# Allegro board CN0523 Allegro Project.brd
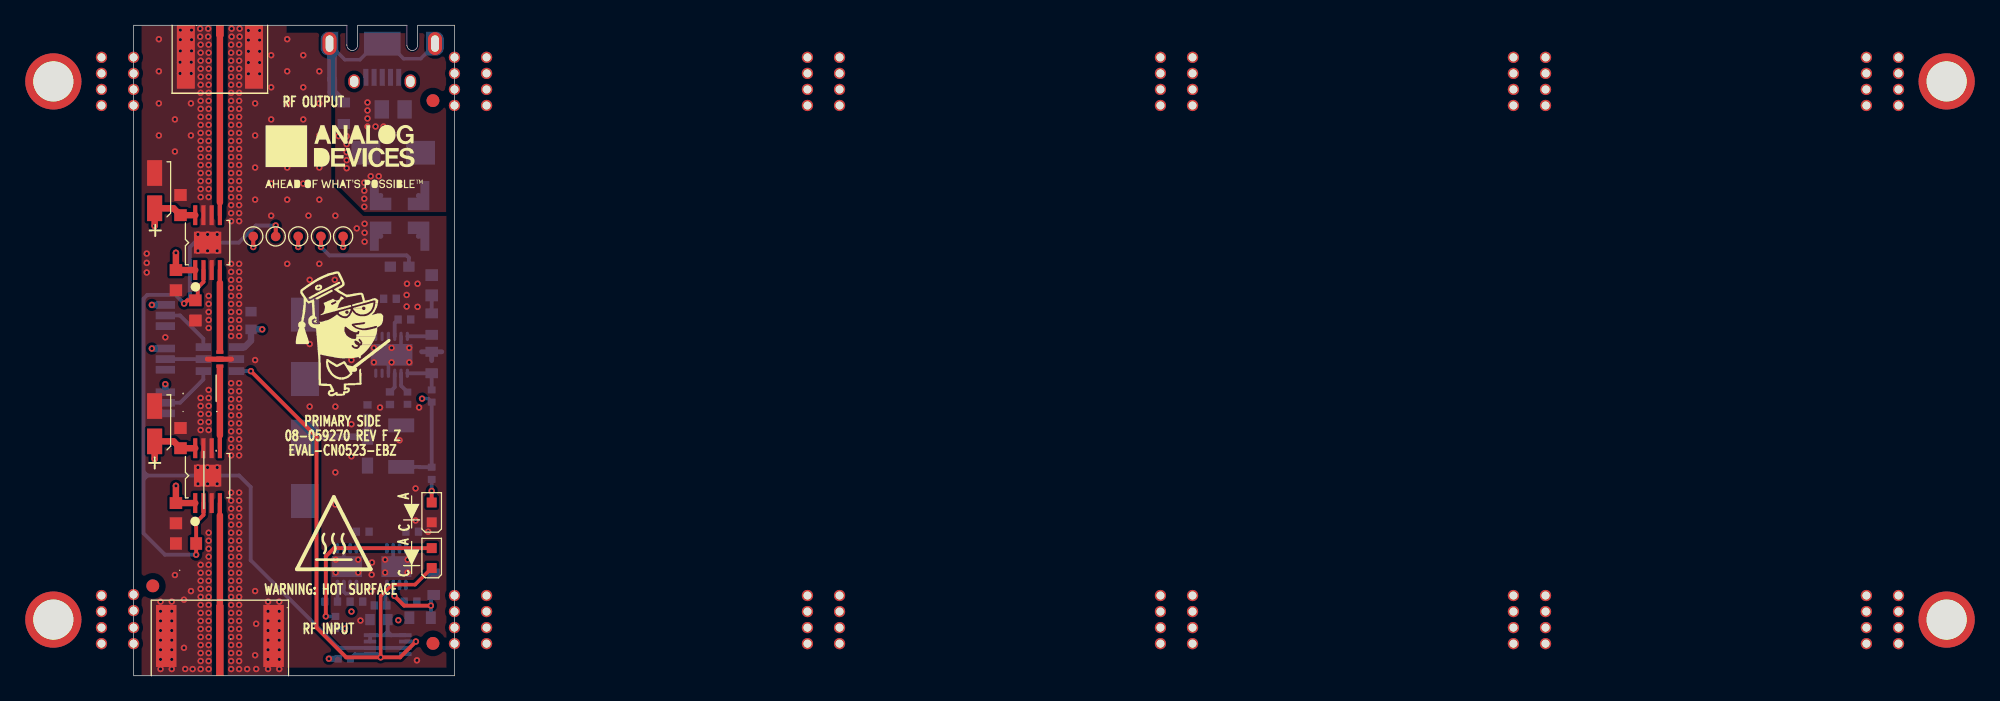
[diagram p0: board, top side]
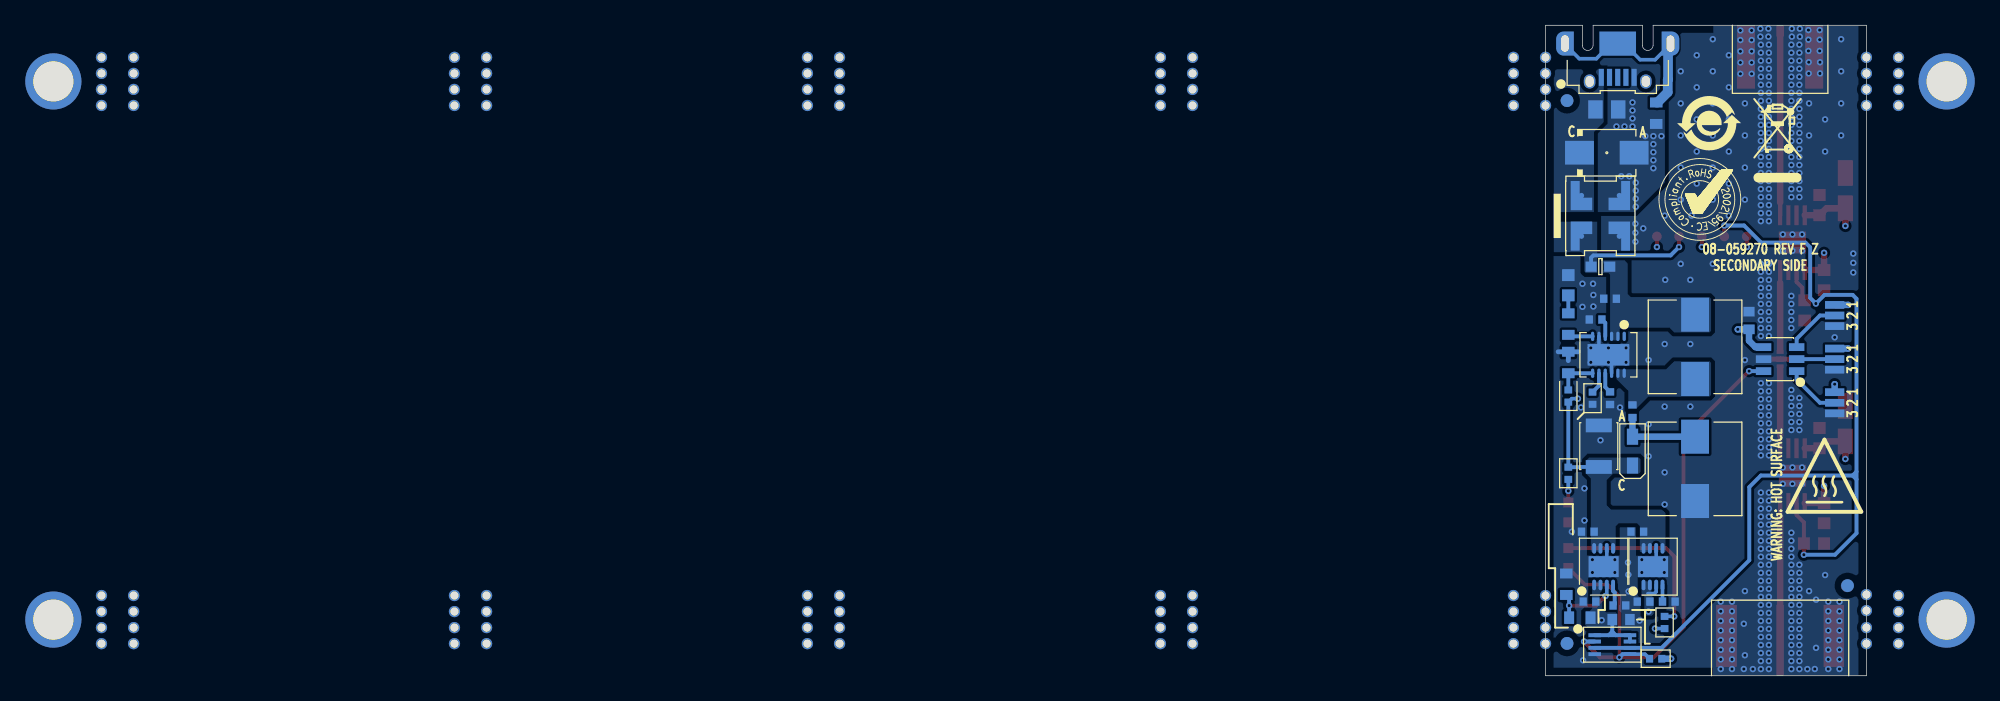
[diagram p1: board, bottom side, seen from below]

Outline 25.4 x 51.49 mm; copper layers: TOP, L2_GND, L3_GND, L4_PWR, L5_GND, BOTTOM. Coordinates in mm from the lower left corner of the outline.
Outline path: 0,51.49 0,0 25.4,0 25.4,51.49 22.49,51.49 22.49,49.92 arc(22.06,49.49) 21.63,49.92 21.63,51.49 17.74,51.49 17.74,49.92 arc(17.31,49.49) 16.88,49.92 16.88,51.49 4.96,51.49 4.97,51.49 0,51.49

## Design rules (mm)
constraint set DEFAULT: min track width 0.279

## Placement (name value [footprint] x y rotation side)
C1  330PF  [C0603]  4.15 10.47 0 top
C2  330PF  [C0603]  3.35 12.87 90 top
C3  330PF  [C0603]  3.71 18.81 270 top
C4  2.2uF  [C3216]  1.67 19.95 90 top
C5  330PF  [C0603]  4.89 28.92 90 top
C6  330PF  [C0603]  3.35 31.32 90 top
C7  330PF  [C0603]  3.71 37.26 270 top
C8  2.2uF  [C3216]  1.67 38.4 90 top
C9  0.1uF  [C0603#2]  9.29 28.12 270 bottom
C10  0.1uF  [C0603#2]  19.42 4.45 0 bottom
C11  4.7uF  [C0402]  18.14 11.4 180 bottom
C12  1000pF  [C0402]  15.64 5.87 0 bottom
C13  4.7uF  [C0402]  17.64 5.87 180 bottom
C23  47UF  [C0805H55]  20.55 44.83 0 bottom
C25  4.7uF  [C0402]  20.29 29.85 180 bottom
C26  3.3NF  [C0603]  23.6 30.91 90 bottom
C27  1uF  [C0402]  21.44 28.2 180 bottom
C28  22UF  [C1210H106]  21.18 18.17 90 bottom
C29  10NF  [C0402]  20.29 21.97 90 bottom
C30  1uF  [C0402]  18.52 20.94 90 bottom
C36  4.7uF  [C0402]  22.05 11.4 180 bottom
C38  1000pF  [C0402]  19.55 5.56 0 bottom
C39  4.7uF  [C0402]  21.92 5.87 180 bottom
D1  SMAJ5.0A-13-F  [DIOSMJ5_0]  20.55 41.4 180 bottom
D2  PMEG3010BEA,115  [SOD323]  18.52 17.78 90 bottom
DS1  150060VS55040  [LED0603-2]  23.6 12.93 90 top
DS2  150060RS55040  [LED0603-2]  23.6 9.32 90 top
E1  120OHM  [L0603]  21.06 32.39 0 bottom
FL1  5.5GHZ  [FL0603-3P-RF]  6.83 25.06 90 top
J1  132365-10  [CNSMARAL686W375H177]  6.83 0 270 top
J2  60312202114513  [CNSMARAL559W250H131]  6.83 51.49 90 top
JP1  3PIN_SOLDER_JUMPER  [JPRSLD03]  2.51 28.52 270 bottom
JP2  3PIN_SOLDER_JUMPER  [JPRSLD03]  2.51 25.06 270 bottom
JP3  3PIN_SOLDER_JUMPER  [JPRSLD03]  2.51 21.61 270 bottom
L3  800OHMS AT 100MEGHZ  [L2020_A]  21.06 36.4 270 bottom
L5  1.5UH  [LSMSQ272H197]  13.56 16.38 270 bottom
L6  1.5UH  [LSMSQ272H197]  13.56 26.04 270 bottom
NOREF  -  []  189.67 175.62 0 top
NOREF#2  -  []  -69.38 311.61 0 top
NOREF#3  -  []  167.86 166.39 0 top
NOREF#4  -  []  18.41 0 90 top
NOREF#5  -  []  55.88 0 0 top
NOREF#6  -  [unnamed#2]  143.51 47.05 0 top
NOREF#7  -  []  -3.73 85.62 0 top
NOREF#8  -  [unnamed#2]  81.28 47.68 0 top
NOREF#9  -  [unnamed#2]  139.7 45.14 0 top
NOREF#10  -  [unnamed#2]  137.16 46.41 0 top
NOREF#11  -  [unnamed#2]  23.7 45.53 0 top
NOREF#12  -  [unnamed#2]  83.82 5.08 0 top
NOREF#13  -  []  45.13 222.88 0 top
NOREF#14  -  []  109.22 0 0 top
NOREF#15  -  [unnamed#2]  0 46.41 0 top
NOREF#16  -  [unnamed#2]  53.34 45.14 0 top
NOREF#17  -  [unnamed#2]  109.22 47.68 0 top
NOREF#18  -  [unnamed#2]  111.76 45.14 0 top
NOREF#19  -  [unnamed#2]  55.88 45.14 0 top
NOREF#20  -  [unnamed#2]  109.22 2.54 0 top
NOREF#21  -  [unnamed#2]  25.4 46.41 0 top
NOREF#22  -  [unnamed#2]  0 6.43 0 top
NOREF#23  -  []  -85.24 -85.99 0 top
NOREF#24  -  []  48.89 171.39 0 top
NOREF#25  -  []  25.02 178.51 0 top
NOREF#26  -  [unnamed#2]  109.22 46.41 0 top
NOREF#27  -  []  40.38 222.88 0 top
NOREF#28  -  [unnamed#2]  53.34 5.08 0 top
NOREF#29  -  [unnamed#2]  -6.35 47.05 0 top
NOREF#30  -  [unnamed#2]  1.52 7.11 0 top
NOREF#31  -  [unnamed#2]  -2.54 6.35 0 top
NOREF#32  -  [unnamed#2]  83.82 46.41 0 top
NOREF#33  -  []  184.92 206.92 90 top
NOREF#34  -  [unnamed#2]  0 48.95 0 top
NOREF#35  -  [unnamed#2]  137.16 45.14 0 top
NOREF#36  -  [unnamed#2]  137.16 5.08 0 top
NOREF#37  -  [unnamed#2]  25.4 47.68 0 top
NOREF#38  -  []  23.49 171.41 0 top
NOREF#39  -  []  53.34 0 0 top
NOREF#40  -  [unnamed#2]  55.88 2.54 0 top
NOREF#41  -  [unnamed#2]  53.34 48.95 0 top
NOREF#42  -  [unnamed#2]  25.4 48.95 0 top
NOREF#43  -  []  48.89 171.39 90 top
NOREF#44  -  [unnamed#2]  109.22 48.95 0 top
NOREF#45  -  [unnamed#2]  53.34 2.54 0 top
NOREF#46  -  [unnamed#2]  81.28 2.54 0 top
NOREF#47  -  [unnamed#2]  139.7 3.81 0 top
NOREF#48  -  [unnamed#2]  55.88 6.35 0 top
NOREF#49  -  []  18.41 51.49 180 top
NOREF#50  -  []  -26.51 203.8 0 top
NOREF#51  -  [unnamed#2]  109.22 45.14 0 top
NOREF#52  -  [unnamed#2]  81.28 45.14 0 top
NOREF#53  -  [unnamed#2]  137.16 3.81 0 top
NOREF#54  -  [unnamed#2]  139.7 46.41 0 top
NOREF#55  -  []  111.76 0 0 top
NOREF#56  -  [unnamed#2]  -2.54 47.68 0 top
NOREF#57  -  [unnamed#2]  83.82 45.14 0 top
NOREF#58  -  [unnamed#2]  0 45.14 0 top
NOREF#59  -  []  81.28 0 0 top
NOREF#60  -  [unnamed#2]  111.76 6.35 0 top
NOREF#61  -  []  0 0 0 top
NOREF#62  -  [unnamed#2]  137.16 2.54 0 top
NOREF#63  -  [unnamed#2]  81.28 6.35 0 top
NOREF#64  -  [unnamed#2]  -2.54 2.54 0 top
NOREF#65  -  [unnamed#2]  0 5.16 0 top
NOREF#66  -  []  -85.24 -85.99 0 top
NOREF#67  -  []  -85.24 -85.99 0 top
NOREF#68  -  [unnamed#2]  0 3.81 0 top
NOREF#69  -  [unnamed#2]  81.28 5.08 0 top
NOREF#70  -  [unnamed#2]  139.7 2.54 0 top
NOREF#71  -  [unnamed#2]  55.88 5.08 0 top
NOREF#72  -  [unnamed#2]  137.16 6.35 0 top
NOREF#73  -  []  194.98 109.04 0 top
NOREF#74  -  []  178.88 195.06 0 top
NOREF#75  -  []  23.49 222.88 0 top
NOREF#76  -  [unnamed#2]  109.22 5.08 0 top
NOREF#77  -  [unnamed#2]  0 47.68 0 top
NOREF#78  -  [unnamed#2]  27.94 48.95 0 top
NOREF#79  -  []  137.16 0 0 top
NOREF#80  -  []  0 0 0 top
NOREF#81  -  [unnamed#2]  111.76 47.68 0 top
NOREF#82  -  [unnamed#2]  -2.54 5.08 0 top
NOREF#83  -  [unnamed#2]  55.88 47.68 0 top
NOREF#84  -  []  176.52 177.28 90 top
NOREF#85  -  [unnamed#2]  83.82 2.54 0 top
NOREF#86  -  []  147.32 0 0 top
NOREF#87  -  [unnamed#2]  111.76 2.54 0 top
NOREF#88  -  [unnamed#2]  143.51 4.45 0 top
NOREF#89  -  [unnamed#2]  111.76 3.81 0 top
NOREF#90  -  [unnamed#2]  111.76 48.95 0 top
NOREF#91  -  []  83.82 0 0 top
NOREF#92  -  []  25.4 0 0 top
NOREF#93  -  [unnamed#2]  55.88 48.95 0 top
NOREF#94  -  []  181.24 212.84 90 top
NOREF#95  -  [unnamed#2]  109.22 6.35 0 top
NOREF#96  -  [unnamed#2]  53.34 46.41 0 top
NOREF#97  -  [unnamed#2]  27.94 3.81 0 top
NOREF#98  -  [unnamed#2]  -2.54 3.81 0 top
NOREF#99  -  [unnamed#2]  25.4 5.08 0 top
NOREF#100  -  [unnamed#2]  111.76 5.08 0 top
NOREF#101  -  [unnamed#2]  139.7 48.95 0 top
NOREF#102  -  []  -2.54 0 0 top
NOREF#103  -  [unnamed#2]  53.34 3.81 0 top
NOREF#104  -  [unnamed#2]  81.28 3.81 0 top
NOREF#105  -  []  14.14 -9.55 0 top
NOREF#106  -  []  -10.16 0 0 top
NOREF#107  -  []  -6.35 4.45 0 top
NOREF#108  -  [unnamed#2]  27.94 6.35 0 top
NOREF#109  -  [unnamed#2]  139.7 47.68 0 top
NOREF#110  -  [unnamed#2]  139.7 6.35 0 top
NOREF#111  -  []  39.96 219.32 0 top
NOREF#112  -  [unnamed#2]  0 2.54 0 top
NOREF#113  -  [unnamed#2]  83.82 48.95 0 top
NOREF#114  -  [unnamed#2]  83.82 6.35 0 top
NOREF#115  -  [unnamed#2]  109.22 3.81 0 top
NOREF#116  -  [unnamed#2]  27.94 5.08 0 top
NOREF#117  -  [unnamed#2]  55.88 46.41 0 top
NOREF#118  -  []  23.49 222.88 0 top
NOREF#119  -  [unnamed#2]  137.16 47.68 0 top
NOREF#120  -  [unnamed#2]  -2.54 48.95 0 top
NOREF#121  -  [unnamed#2]  111.76 46.41 0 top
NOREF#122  -  []  139.7 0 0 top
NOREF#123  -  [unnamed#2]  83.82 47.68 0 top
NOREF#124  -  [unnamed#2]  27.94 45.14 0 top
NOREF#125  -  []  46.05 222.88 0 top
NOREF#126  -  [unnamed#2]  27.94 2.54 0 top
NOREF#127  -  [unnamed#2]  25.4 2.54 0 top
NOREF#128  -  [unnamed#2]  25.4 45.14 0 top
NOREF#129  -  []  16.36 41.07 0 top
NOREF#130  -  [unnamed#2]  27.94 46.41 0 top
NOREF#131  -  []  27.94 0 0 top
NOREF#132  -  []  0 51.49 270 top
NOREF#133  -  [unnamed#2]  81.28 48.95 0 top
NOREF#134  -  [unnamed#2]  -2.54 45.14 0 top
NOREF#135  -  [unnamed#2]  137.16 48.95 0 top
NOREF#136  -  [unnamed#2]  81.28 46.41 0 top
NOREF#137  -  []  25.02 178.51 0 top
NOREF#138  -  []  -10.16 0 0 top
NOREF#139  -  []  -10.16 51.49 0 top
NOREF#140  -  []  23.49 171.41 0 top
NOREF#141  -  [unnamed#2]  53.34 6.35 0 top
NOREF#142  -  [unnamed#2]  139.7 5.08 0 top
NOREF#143  -  []  178.88 209.23 0 top
NOREF#144  -  [unnamed#2]  -2.54 46.41 0 top
NOREF#145  -  [unnamed#2]  55.88 3.81 0 top
NOREF#146  -  [unnamed#2]  25.4 3.81 0 top
NOREF#147  -  []  16.59 27.07 0 top
NOREF#148  -  []  167.86 206.94 0 top
NOREF#149  -  []  41.23 222.88 0 top
NOREF#150  -  [unnamed#2]  -6.35 4.45 0 top
NOREF#151  -  [unnamed#2]  23.7 2.56 0 top
NOREF#152  -  [unnamed#2]  83.82 3.81 0 top
NOREF#153  -  []  10.01 92.28 0 top
NOREF#154  -  [unnamed#2]  53.34 47.68 0 top
NOREF#155  -  [unnamed#2]  25.4 6.35 0 top
NOREF#156  -  []  -6.35 4.45 0 top
NOREF#157  -  [unnamed#2]  27.94 47.68 0 top
NOREF#158  -  [unnamed#2]  1.5 7.13 180 bottom
NOREF#159  -  [unnamed#2]  23.7 45.53 180 bottom
NOREF#160  -  []  7.24 39.12 180 bottom
NOREF#161  -  [unnamed#2]  23.7 2.56 180 bottom
NOREF#162  -  []  13.72 48.77 180 bottom
P1  47590-0001  [CNMOLEX47590-0001]  19.69 51.49 270 bottom
R1  1K  [R0603]  16.64 44.53 270 bottom
R2  10K  [R0402]  16.68 1.35 0 bottom
R3  20K  [R0402]  21.68 21.97 90 bottom
R4  22.1K  [R0603]  23.6 27.84 90 bottom
R5  1MEG  [R0402]  23.6 22.14 90 bottom
R6  402K  [R0603]  23.6 24.8 90 bottom
R7  619  [R0402]  15.98 4.22 270 bottom
R8  150  [R0402]  23.6 16.03 90 bottom
R9  1K  [R0603]  22.68 4.6 0 bottom
R10  6.49K  [R0603]  23.75 7.24 90 bottom
TP1  TESTPAD  [TPSMC30]  11.25 34.78 0 top
TP2  TESTPAD  [TPSMC30]  14.83 34.78 0 top
TP3  TESTPAD  [TPSMC30]  9.47 34.78 0 top
TP4  TESTPAD  [TPSMC30]  13.03 34.78 0 top
TP5  TESTPAD  [TPSMC30]  16.59 34.78 0 top
U1  ADT6401SRJZ  [TSOT23_6]  6.83 25.06 90 bottom
U2  LT8364EDE#PBF  [DFN12_4X3_PAD3_3X1_7]  20.42 25.41 0 bottom
U3  NLV27WZ126USG  [US8-2]  20.11 2.46 270 bottom
U4  ADM7170ACPZ-3.3  [DFN8_3X3_PAD2_38X1_64]  20.8 8.64 180 bottom
U5  ADM7171ACPZ-5.0  [DFN8_3X3_PAD2_38X1_64]  16.89 8.64 180 bottom
U6  HMC407MS8GE  [MSOP8_PAD2_16X1_73]  5.86 15.84 0 top
U7  HMC407MS8GE  [MSOP8_PAD2_16X1_73]  5.86 34.29 0 top

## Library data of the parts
C1-C3 C5-C7 = CAP: User Part Number: UPN; Tolerance: 5; alternate symbols: (C0603); part number: CAP_SM-330PF,50V,5,E042934,C0603; tolerance: 5
C4 C8 = CAPP: Tolerance: 10; User Part Number: UPN; alternate symbols: (C3216); part number: CAPP_SM-2.2UF,25V,10,E000692,C3216; tolerance: 10
C9 C10 = CAP: User Part Number: UPN; Tolerance: 10; alternate symbols: (C0603L); part number: CAP_SM-0.1UF,16V,10,E015036,C0603; tolerance: 10
C11 C13 C25 C36 C39 = CAP: User Part Number: UPN; Tolerance: 20; alternate symbols: (C0402); part number: CAP_SM-4.7UF,6.3V,20,E014207,C0402; tolerance: 20
C12 C38 = CAP: User Part Number: UPN; Tolerance: 5; alternate symbols: (C0402); part number: CAP_SM-1000PF,50V,5,E012419,C0402; tolerance: 5
C23 = CAP: User Part Number: UPN; Tolerance: 20; alternate symbols: (C0805H55); part number: CAP_SM-47UF,6.3V,20,E048007,C0805H55; tolerance: 20
C26 = CAP: User Part Number: UPN; Tolerance: 10; alternate symbols: (C0603); part number: CAP_SM-3.3NF,50V,10,E060118,C0603; tolerance: 10
C27 C30 = CAP: User Part Number: UPN; Tolerance: 20; alternate symbols: (C0402); part number: CAP_SM-1UF,16V,20,E020695,C0402; tolerance: 20
C28 = CAP: Tolerance: 10; User Part Number: UPN; alternate symbols: (C1210H106); part number: CAP_SM-22UF,25V,10,E054041,C1210H106; tolerance: 10
C29 = CAP: User Part Number: UPN; Tolerance: 5; alternate symbols: (C0402); part number: CAP_SM-10NF,16V,5,E042671,C0402; tolerance: 5
D1 = DIO: Tolerance: N/A; User Part Number: UPN; alternate symbols: (DIOSMJ5_0); part number: DIO_SM-SMAJ5.0A-13-F,5V,N/A,E001108,DIOSMJ5_0; tolerance: N/A
D2 = DIOSCHOTTKY: Tolerance: N/A; User Part Number: UPN; alternate symbols: (SOD323); part number: DIOSCHOTTKY_SM-PMEG3010BEA,115,30V,N/A,E014012,SOD323; tolerance: N/A
DS1 = DIOLED: Tolerance: N/A; User Part Number: UPN; alternate symbols: (LED0603-2); part number: DIOLED_SM-150060VS55040,2.4V,N/A,E056632,LED0603-2; tolerance: N/A
DS2 = DIOLED: Tolerance: N/A; User Part Number: UPN; alternate symbols: (LED0603-2); part number: DIOLED_SM-150060RS55040,2.4V,N/A,E056631,LED0603-2; tolerance: N/A
E1 = FERRITE: Tolerance: 25; User Part Number: UPN; alternate symbols: (L0603); part number: FERRITE_SM-120OHM,25,E012242,L0603; tolerance: 25
FL1 = FLTRBP3P_V6: User Part Number: UPN; Tolerance: N/A; alternate symbols: (FL0603-3P-RF); part number: FLTRBP3P_V6_SM-5.5GHZ,E060424,FL0603-3P-RF; tolerance: N/A
J1 = CNBNC5P: Tolerance: N/A; User Part Number: UPN; alternate symbols: (CNSMARAL686W375H177_HMC407); part number: CNBNC5P_SM-132365-10,E033180,CNSMARAL686W375H177; tolerance: N/A
J2 = CNBNC5P: User Part Number: UPN; Tolerance: N/A; alternate symbols: (CNSMARAL559W250H131); part number: CNBNC5P_SM-60312202114513,E049020,CNSMARAL559W250H131; tolerance: N/A
JP1-JP3 = NC3P_JMPR: Tolerance: N/A; User Part Number: UPN; alternate symbols: (JPRSLD03); part number: NC3P_JMPR_SM-3PIN_SOLDER_JUMPER,E005606,JPRSLD03; tolerance: N/A
L3 = CHOKE4P: User Part Number: UPN; Tolerance: N/A; alternate symbols: (L2020_A); part number: CHOKE4P_SM-800OHMS AT 100MEGHZ,N/A,E027130,L2020_A; tolerance: N/A
L5 L6 = IND: Tolerance: 20; User Part Number: UPN; alternate symbols: (LSMSQ272H197); part number: IND_SM-1.5UH,20,E044944,LSMSQ272H197; tolerance: 20
P1 = CN5P_3SHLD: User Part Number: UPN; Tolerance: N/A; alternate symbols: (CNMOLEX47590-0001); part number: CN5P_3SHLD_SM-47590-0001,E015753,CNMOLEX47590-0001; tolerance: N/A
R1 R9 = RES: User Part Number: UPN; Tolerance: 1; alternate symbols: (R0603); part number: RES_SM-1K,E003678,1/10W,1,R0603; tolerance: 1
R2 = RES: Tolerance: 1; User Part Number: UPN; alternate symbols: (R0402); part number: RES_SM-10K,E003751,1/10W,1,R0402; tolerance: 1
R3 = RES: Tolerance: 1; User Part Number: UPN; alternate symbols: (R0402); part number: RES_SM-20K,E003791,1/10W,1,R0402; tolerance: 1
R4 = RES: User Part Number: UPN; Tolerance: 1; alternate symbols: (R0603); part number: RES_SM-22.1K,E003681,1/10W,1,R0603; tolerance: 1
R5 = RES: Tolerance: 1; User Part Number: UPN; alternate symbols: (R0402); part number: RES_SM-1MEG,E003749,1/10W,1,R0402; tolerance: 1
R6 = RES: User Part Number: UPN; Tolerance: 1; alternate symbols: (R0603); part number: RES_SM-402K,E026771,1/10W,1,R0603; tolerance: 1
R7 = RES: Tolerance: 1; User Part Number: UPN; alternate symbols: (R0402); part number: RES_SM-619,E006549,1/10W,1,R0402; tolerance: 1
R8 = RES: Tolerance: 1; User Part Number: UPN; alternate symbols: (R0402); part number: RES_SM-150,E017444,1/10W,1,R0402; tolerance: 1
R10 = RES: User Part Number: UPN; Tolerance: 1; alternate symbols: (R0603); part number: RES_SM-6.49K,E050706,1/10W,1,R0603; tolerance: 1
TP1-TP5 = NCTESTPAD: Tolerance: N/A; User Part Number: UPN; alternate symbols: (TPSMC30); part number: NCTESTPAD_SM-TESTPAD,E012884,TPSMC30; tolerance: N/A
U1 = ADT6401: User Part Number: UPN; Tolerance: N/A; alternate symbols: (TSOT23_6); part number: ADT6401_SM-ADT6401SRJZ,E038244,TSOT23_6; tolerance: N/A
U2 = ADLT8364_V2: User Part Number: UPN; Tolerance: N/A; alternate symbols: (DFN12_4X3_PAD3_3X1_7); part number: ADLT8364_V2_SM-LT8364EDE#PBF,E038568,DFN12_4X3_PAD3_3X1_7; tolerance: N/A
U3 = ICNL27WZ126: Tolerance: N/A; User Part Number: UPN; alternate symbols: (US8-2); part number: ICNL27WZ126_SM-NLV27WZ126USG,E060395,US8-2; tolerance: N/A
U4 = ADM7170: Tolerance: N/A; User Part Number: UPN; alternate symbols: (DFN8_3X3_PAD2_38X1_64); part number: ADM7170_SM-ADM7170ACPZ-3.3,E022590,DFN8_3X3_PAD2_38X1_64; tolerance: N/A
U5 = ADM7171: Tolerance: N/A; User Part Number: UPN; alternate symbols: (DFN8_3X3_PAD2_38X1_64); part number: ADM7171_SM-ADM7171ACPZ-5.0,E022768,DFN8_3X3_PAD2_38X1_64; tolerance: N/A
U6 U7 = ADHMC407: Tolerance: N/A; User Part Number: UPN; alternate symbols: (MSOP8_PAD2_16X1_73); part number: ADHMC407_SM-HMC407MS8GE,E055304,MSOP8_PAD2_16X1_73; tolerance: N/A

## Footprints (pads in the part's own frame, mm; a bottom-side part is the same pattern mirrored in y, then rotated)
C0402
  rect 0.584x0.66 smd: 1(-0.5,0) 2(0.5,0)
C0603
  rect 0.94x0.991 smd: 1(-0.8,0) 2(0.8,0)
C0603#2
  rect 0.762x0.889 smd: 1(-0.7,0) 2(0.7,0)
C0805H55
  rect 1.143x1.448 smd: 1(-0.9,0) 2(0.9,0)
C1210H106
  rect 1.092x2.057 smd: 1(-1.646,0) 2(1.646,0)
C3216
  rect 2.032x1.194 smd: N(1.397,0) P(-1.397,0)
CNMOLEX47590-0001
  oval 1.118x0.914 hole 0.864x0.66: (4.45,-2.225) (4.45,2.225)
  rect 1.346x0.406 smd: 1(4.123,-1.3) 2(4.123,-0.65) 3(4.123,0) 4(4.123,0.65) 5(4.123,1.3)
  oval 1.803x1.118 hole 1.295x0.61: SH1(1.45,4.175) SH3(1.45,-4.175)
  rect 1.905x2.896 smd: SH2(1.45,0)
CNSMARAL559W250H131
  rect 0.889x0.61 smd: 1(-0.445,0)
  rect 5.004x1.397 smd: 2(-2.502,2.702) 3(-2.502,-2.702) 4(-2.502,2.702) 5(-2.502,-2.702)
CNSMARAL686W375H177
  rect 5.613x0.584 smd: 1(-2.807,0)
  rect 4.902x1.6 smd: 2(-3.151,4.25) 3(-3.151,4.25) 4(-3.151,-4.25) 5(-3.151,-4.25)
DFN8_3X3_PAD2_38X1_64
  oval 0.305x0.838 smd: 1(-0.75,-1.45) 2(-0.25,-1.45) 3(0.25,-1.45) 4(0.75,-1.45) 5(0.75,1.45) 6(0.25,1.45) 7(-0.25,1.45) 8(-0.75,1.45)
  rect 2.388x1.651 smd: PAD(0,0)
DFN12_4X3_PAD3_3X1_7
  oval 0.254x0.737 smd: 1(-1.25,-1.46) 2(-0.75,-1.46) 3(-0.25,-1.46) 4(0.25,-1.46) 5(0.75,-1.46) 6(1.25,-1.46) 7(1.25,1.46) 8(0.75,1.46) 9(0.25,1.46) 10(-0.25,1.46) 11(-0.75,1.46) 12(-1.25,1.46)
  rect 3.302x1.702 smd: PAD(0,0)
DIOSMJ5_0
  rect 2.286x1.88 smd: A(2.164,0) C(-2.164,0)
FL0603-3P-RF
  rect 0.254x0.559 smd: 1(-0.559,0) 3(0.559,0)
  rect 0.406x0.61 smd: 2(0,0)
JPRSLD03
  rect 0.61x1.524 smd: 1(-0.838,0) 2(0,0) 3(0.838,0)
L0603
  rect 0.889x0.813 smd: 1(-0.737,0) 2(0.737,0)
L2020_A
  custom 0.425x0.425 smd: 1(-1.606,-1.501) 2(1.606,-1.501) 3(1.606,1.501) 4(-1.606,1.501)
LED0603-2
  rect 0.787x0.787 smd: A(0.787,0) C(-0.787,0)
LSMSQ272H197
  rect 2.692x2.21 smd: 1(-2.546,0) 2(2.546,0)
MSOP8_PAD2_16X1_73
  rect 0.33x1.575 smd: 1(-0.975,-2.171) 2(-0.325,-2.171) 3(0.325,-2.171) 4(0.975,-2.171) 5(0.975,2.171) 6(0.325,2.171) 7(-0.325,2.171) 8(-0.975,2.171)
  rect 2.159x1.727 smd: PAD(0,0)
R0402
  rect 0.559x0.61 smd: 1(-0.483,0) 2(0.483,0)
R0603
  rect 0.787x0.991 smd: 1(-0.85,0) 2(0.85,0)
SOD323
  rect 1.27x0.889 smd: A(1.143,0) C(-1.143,0)
TPSMC30
  round 0.762 smd: 1(0,0)
TSOT23_6
  rect 0.61x1.219 smd: 1(-0.95,-1.31) 2(0,-1.31) 3(0.95,-1.31) 4(0.95,1.31) 5(0,1.31) 6(-0.95,1.31)
unnamed#2
  round 4.445 hole 3.175 unplated: (0,0)
US8-2
  rect 0.305x0.991 smd: 1(-0.75,-1.395) 2(-0.25,-1.395) 3(0.25,-1.395) 4(0.75,-1.395) 5(0.75,1.395) 6(0.25,1.395) 7(-0.25,1.395) 8(-0.75,1.395)

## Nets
3V8: C10.2(N2) C39.2(N2) R2.1 R7.2(N2) R9.1 TP4.1(N1) U3.1 U3.7 U3.8 U4.1 U4.2(VOUT2)
5V0: C2.2(N2) C3.2(N2) C4.P C6.2(N2) C7.2(N2) C8.P C9.2(N2) C13.2(N2) JP1.1 JP2.1 JP3.1 TP3.1(N1) U1.4(VCC) U5.1 U5.2(VOUT2) U5.3 U6.1 U6.8 U7.1 U7.8
5V6: C11.2(N2) C28.1 C36.2(N2) D2.C R5.1 R8.2(N2) TP5.1(N1) U4.5 U4.7 U4.8 U5.5 U5.7 U5.8
5V_USB: E1.2(N2) L3.2 TP2.1(N1)
GND: C1.1 C2.1 C3.1 C4.N(N2) C5.1 C6.1 C7.1 C8.N(N2) C9.1 C10.1 C11.1 C12.1 C13.1 C25.1 C26.2(N2) C27.1 C28.2(N2) C29.1 C36.1 C38.1 C39.1 DS1.C FL1.2 J1.2 J1.3 J1.4 J1.5(SH4) J2.2 J2.3 J2.4 J2.5(SH4) JP1.3 JP2.3 JP3.3 L3.3 L5.2(N2) R3.1 R6.2(N2) R10.2(N2) U1.5 U2.5 U2.10 U2.PAD U3.4 U4.6 U4.PAD U5.6 U5.PAD U6.3 U6.6 U6.7 U6.PAD U7.3 U7.6 U7.7 U7.PAD
PGND: C23.1 D1.A(P) L3.4(N4) P1.5 R1.2(N2)
S0: JP1.2(COM) U1.3
S1: JP2.2(COM) U1.2
S2: JP3.2(COM) U1.1
UNNAMED_3_ADLT8364V2_I56_EN: C25.2(N2) E1.1 L6.1 U2.2 U2.3(VIN)
UNNAMED_3_ADLT8364V2_I56_FBX: R5.2(N2) R6.1 U2.7
UNNAMED_3_ADLT8364V2_I56_INTVCC: C27.2(N2) U2.4
UNNAMED_3_ADLT8364V2_I56_RT: R3.2(N2) U2.8
UNNAMED_3_ADLT8364V2_I56_SS: C29.2(N2) U2.9
UNNAMED_3_ADLT8364V2_I56_SW1: C30.2(N2) L6.2(N2) U2.11 U2.12
UNNAMED_3_ADLT8364V2_I56_VC: R4.1 U2.6
UNNAMED_3_ADM7170_I92_SENSE: R9.2(N2) R10.1 U4.3
UNNAMED_3_ADM7170_I92_SS: C38.2(N2) U4.4
UNNAMED_3_ADM7171_I103_SS: C12.2(N2) U5.4
UNNAMED_3_CAP_I59_N1: C26.1 R4.2(N2)
UNNAMED_3_CAP_I80_N2: C23.2(N2) D1.C L3.1 P1.1
UNNAMED_3_CN5P3SHLD_I3_N6: P1.SH1 P1.SH2 P1.SH3(N8) R1.1
UNNAMED_3_DIOLED_I28_P: DS1.A(P) R8.1
UNNAMED_3_DIOSCHOTTKY_I63_P: C30.1 D2.A(P) L5.1
UNNAMED_8_ADHMC407_I276_RFIN: J1.1 U6.4
UNNAMED_8_ADHMC407_I276_RFOUT: FL1.1 U6.5
UNNAMED_8_ADHMC407_I289_RFIN: FL1.3(I/O_2) U7.4
UNNAMED_8_ADHMC407_I289_RFOUT: J2.1 U7.5
UNNAMED_8_ADT6401_I72_TOVERN: DS2.C R2.2(N2) U1.6 U3.2 U3.5
UNNAMED_8_DIOLED_I133_P: DS2.A(P) R7.1
VPD: C1.2(N2) C5.2(N2) TP1.1(N1) U3.3(Y2) U3.6 U6.2(VPD) U7.2(VPD)

Pads without a net: P1 2 3 4; U2 1

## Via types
v1: diameter 0.508, hole 0.254, TOP to BOTTOM, 437 vias

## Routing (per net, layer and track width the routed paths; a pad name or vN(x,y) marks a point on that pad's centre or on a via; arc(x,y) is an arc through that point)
3V8: length 7.4
  TOP w0.318: v1(13.03,33.94) TP4.1
  BOTTOM w0.279: R7.2 v1(16.74,3.73)
  BOTTOM w0.305: 20.12,3.49 20.12,3.49 20.4,3.21 ; 20.12,3.49 C10.2 ; 20.12,3.49 19.84,3.21 ; 19.84,3.21 U3.8 U3.7 ; 19.84,3.21 20.4,3.21 ; U3.1 20.4,3.21
  BOTTOM w0.508: R2.1 v1(15.46,1.35)
  vias: v1(20.96,4.39)
5V0: length 23.5
  TOP w0.318: TP3.1 v1(9.47,33.93)
  TOP w0.508: v1(1.67,35.61) C8.P 3.17,37 C7.2 U7.8 ; v1(3.35,33.48) C6.2 U7.1 ; v1(3.35,15.03) C2.2 U6.1 ; U6.8 C3.2 3.17,18.56 C4.P v1(1.67,17.16)
  BOTTOM w0.279: 17.3,6.5 16.79,6.5 16.64,6.65 U5.3
  BOTTOM w0.508: U1.4 8.78,26.01 9.29,26.52 C9.2 v1(10.18,27.42) ; JP2.1 v1(1.45,25.9) ; JP3.1 v1(2.51,23.08) ; JP1.1 v1(1.45,29.36)
  vias: v1(17.25,5.08)
5V6: length 23.9
  TOP w0.279: TP5.1 v1(16.59,33.94)
  L4_PWR w0.279: v1(22.83,21.94) 22.83,27 16.59,33.25 v1(16.59,33.94)
  BOTTOM w0.279: R5.1 23.32,21.94 v1(22.83,21.94)
  BOTTOM w0.305: R5.1 R8.2 22.64,16.51 22.63,16.53 C28.1
5V_USB: length 8.9
  TOP w0.318: TP2.1 v1(14.83,33.94)
  BOTTOM w0.305: E1.2 21.79,33.1 21.62,33.27 15.5,33.27 v1(14.83,33.94)
GND: length 10.6
  TOP w0.406: 5.84,25.06 FL1.2 7.75,25.06
  BOTTOM w0.279: U5.6 16.64,8.89 U5.PAD ; U2.10 20.17,25.16 U2.PAD 21.17,26.16 U2.5 ; U4.PAD 20.55,8.89 U4.6
  BOTTOM w0.381: 22.8,25.65 R6.2 ; R6.2 24.4,25.65 ; R6.2 23.6,24.95
  vias: v1(1.04,33.42) v1(1.04,32.68) v1(1.04,31.92) v1(2,50.39) v1(2,47.85) v1(2,45.31) v1(2,42.77) v1(2.13,5.86) v1(2.13,5.1) v1(2.13,4.34) v1(2.13,3.58) v1(2.13,2.82) v1(2.13,2.05) v1(2.13,1.29) v1(2.13,0.53) v1(2.51,26.79) v1(3.02,5.87) v1(3.02,5.11) v1(3.02,4.34) v1(3.02,3.58) v1(3.02,2.82) v1(3.02,2.05) v1(3.02,1.29) v1(3.02,0.53) v1(3.27,44.04) v1(3.27,41.5) v1(3.27,7.97) v1(3.68,48.57) v1(3.68,47.68) v1(3.7,51.11) v1(3.7,50.35) v1(3.7,49.46) v1(3.99,6.02) v1(3.99,2.21) v1(4.09,0.53) v1(4.59,51.11) v1(4.59,50.35) v1(4.59,49.46) v1(4.57,48.57) v1(4.57,47.68) v1(4.54,45.31) v1(4.54,42.77) v1(4.54,6.7) v1(4.67,0.53) v1(5.1,34.93) v1(5.1,33.64) v1(5.1,16.49) v1(5.1,15.19) v1(5.27,51.23) v1(5.27,50.59) v1(5.31,49.96) v1(5.31,49.32) v1(5.31,48.69) v1(5.31,48.05) v1(5.31,47.42) v1(5.31,46.78) v1(5.31,46.15) v1(5.31,45.51) v1(5.31,44.88) v1(5.31,44.24) v1(5.31,43.61) v1(5.31,42.97) v1(5.31,42.34) v1(5.31,41.7) v1(5.31,41.07) v1(5.31,40.43) v1(5.31,39.8) v1(5.31,39.16) v1(5.31,38.53) v1(5.31,37.89) v1(5.31,21.99) v1(5.31,21.36) v1(5.31,20.72) v1(5.31,20.09) v1(5.31,19.45) v1(5.31,8.78) v1(5.31,8.15) v1(5.31,7.51) v1(5.31,6.88) v1(5.31,6.24) v1(5.31,5.61) v1(5.31,4.97) v1(5.31,4.34) v1(5.31,3.7) v1(5.31,3.07) v1(5.31,2.43) v1(5.31,1.8) v1(5.31,1.16) v1(5.31,0.53) v1(5.86,34.93) v1(5.86,33.64) v1(5.86,16.49) v1(5.86,15.19) v1(5.91,51.23) v1(5.91,50.59) v1(5.94,49.96) v1(5.94,49.32) v1(5.94,48.69) v1(5.94,48.05) v1(5.94,47.42) v1(5.94,46.78) v1(5.94,46.15) v1(5.94,45.51) v1(5.94,44.88) v1(5.94,44.24) v1(5.94,43.61) v1(5.94,42.97) v1(5.94,42.34) v1(5.94,41.7) v1(5.94,41.07) v1(5.94,40.43) v1(5.94,39.8) v1(5.94,39.16) v1(5.94,38.53) v1(5.94,37.89) v1(5.94,30.07) v1(5.94,29.43) v1(5.94,28.8) v1(5.94,28.16) v1(5.94,27.53) v1(5.94,22.63) v1(5.94,21.99) v1(5.94,21.36) v1(5.94,20.72) v1(5.94,20.09) v1(5.94,19.45) v1(5.94,11.32) v1(5.94,10.69) v1(5.94,10.05) v1(5.94,9.42) v1(5.94,8.78) v1(5.94,8.15) v1(5.94,7.51) v1(5.94,6.88) v1(5.94,6.24) v1(5.94,5.61) v1(5.94,4.97) v1(5.94,4.34) v1(5.94,3.7) v1(5.94,3.07) v1(5.94,2.43) v1(5.94,1.8) v1(5.94,1.16) v1(5.94,0.53) v1(6.62,34.93) v1(6.62,33.64) v1(6.62,16.49) v1(6.62,15.19) v1(7.76,51.23) v1(7.76,50.59) v1(7.72,49.96) v1(7.72,49.32) v1(7.72,48.69) v1(7.72,48.05) v1(7.72,47.42) v1(7.72,46.78) v1(7.72,46.15) v1(7.72,45.51) v1(7.72,44.88) v1(7.72,44.24) v1(7.72,43.61) v1(7.72,42.97) v1(7.72,42.34) v1(7.72,41.7) v1(7.72,41.07) v1(7.72,40.43) v1(7.72,39.8) v1(7.72,39.16) v1(7.72,38.53) v1(7.72,37.89) v1(7.72,37.26) v1(7.72,36.62) v1(7.72,35.99) v1(7.72,32.61) v1(7.72,31.97) v1(7.72,31.34) v1(7.72,30.7) v1(7.72,30.07) v1(7.72,29.43) v1(7.72,28.8) v1(7.72,28.16) v1(7.72,27.53) v1(7.72,26.89) v1(7.72,23.16) v1(7.72,22.52) v1(7.72,21.89) v1(7.72,21.25) v1(7.72,20.62) v1(7.72,19.98) v1(7.72,19.35) v1(7.72,18.71) v1(7.72,18.08) v1(7.72,17.44) v1(7.72,14.5) v1(7.72,13.86) v1(7.72,13.23) v1(7.72,12.59) v1(7.72,11.96) v1(7.72,11.32) v1(7.72,10.69) v1(7.72,10.05) v1(7.72,9.42) v1(7.72,8.78) v1(7.72,8.15) v1(7.72,7.51) v1(7.72,6.88) v1(7.72,6.24) v1(7.72,5.61) v1(7.72,4.97) v1(7.72,4.34) v1(7.72,3.7) v1(7.72,3.07) v1(7.72,2.43) v1(7.72,1.8) v1(7.72,1.16) v1(7.72,0.53) v1(8.39,51.23) v1(8.39,50.59) v1(8.36,49.96) v1(8.36,49.32) v1(8.36,48.69) v1(8.36,48.05) v1(8.36,47.42) v1(8.36,46.78) v1(8.36,46.15) v1(8.36,45.51) v1(8.36,44.88) v1(8.36,44.24) v1(8.36,43.61) v1(8.36,42.97) v1(8.36,42.34) v1(8.36,41.7) v1(8.36,41.07) v1(8.36,40.43) v1(8.36,39.8) v1(8.36,39.16) v1(8.36,38.53) v1(8.36,37.89) v1(8.36,37.26) v1(8.36,36.62) v1(8.36,35.99) v1(8.36,32.61) v1(8.36,31.97) v1(8.36,31.34) v1(8.36,30.7) v1(8.36,30.07) v1(8.36,29.43) v1(8.36,28.8) v1(8.36,28.16) v1(8.36,27.53) v1(8.36,26.89) v1(8.36,23.16) v1(8.36,22.52) v1(8.36,21.89) v1(8.36,21.25) v1(8.36,20.62) v1(8.36,19.98) v1(8.36,19.35) v1(8.36,18.71) v1(8.36,18.08) v1(8.36,17.44) v1(8.36,14.5) v1(8.36,13.86) v1(8.36,13.23) v1(8.36,12.59) v1(8.36,11.96) v1(8.36,11.32) v1(8.36,10.69) v1(8.36,10.05) v1(8.36,9.42) v1(8.36,8.78) v1(8.36,8.15) v1(8.36,7.51) v1(8.36,6.88) v1(8.36,6.24) v1(8.36,5.61) v1(8.36,4.97) v1(8.36,4.34) v1(8.36,3.7) v1(8.36,3.07) v1(8.36,2.43) v1(8.36,1.8) v1(8.36,1.16) v1(8.36,0.53) v1(8.99,0.53) v1(9.09,51.08) v1(9.09,50.32) v1(9.09,49.43) v1(9.09,48.54) v1(9.09,47.65) v1(9.62,45.31) v1(9.62,42.77) v1(9.62,40.23) v1(9.62,37.69) v1(9.62,24.99) v1(9.62,6.7) v1(9.62,1.62) v1(9.7,4.11) v1(9.7,0.53) v1(9.98,51.08) v1(9.98,50.32) v1(9.98,49.43) v1(9.98,48.54) v1(9.98,47.65) v1(10.64,5.86) v1(10.64,5.1) v1(10.64,4.34) v1(10.64,3.58) v1(10.64,2.82) v1(10.64,2.05) v1(10.64,1.29) v1(10.64,0.53) v1(10.89,49.12) v1(10.89,46.58) v1(10.89,44.04) v1(10.89,41.5) v1(10.89,38.96) v1(10.89,36.42) v1(11.53,5.87) v1(11.53,5.1) v1(11.53,4.34) v1(11.53,3.58) v1(11.53,2.82) v1(11.53,2.05) v1(11.53,1.29) v1(11.53,0.53) v1(12.16,50.39) v1(12.16,47.85) v1(12.16,45.31) v1(12.16,42.77) v1(12.16,40.23) v1(12.16,37.69) v1(12.16,32.61) v1(13.43,49.12) v1(13.43,46.58) v1(13.43,44.04) v1(13.43,41.5) v1(13.43,38.96) v1(13.84,36.42) v1(13.94,31.34) v1(13.94,26.26) v1(13.94,21.31) v1(14.7,47.85) v1(14.7,45.31) v1(14.7,42.77) v1(14.7,40.23) v1(14.7,37.69) v1(14.7,32.61) v1(15.97,36.42) v1(15.93,31.34) v1(15.97,26.26) v1(15.97,21.31) v1(15.97,16.1) v1(15.97,13.56) v1(16,9.19) v1(16,8.17) v1(17.24,24.99) v1(17.24,19.91) v1(17.24,17.37) v1(17.66,35.42) v1(17.78,9.19) v1(17.78,8.17) v1(17.96,4.37) v1(18.29,35.78) v1(18.29,35.07) v1(18.29,34.36) v1(18.87,8.97) v1(18.85,8) v1(18.82,6.68) v1(19.02,25.95) v1(19.02,24.81) v1(19.51,21.23) v1(19.91,9.19) v1(19.91,8.17) v1(20.42,25.95) v1(20.42,24.81) v1(21.05,18.64) v1(21.64,31.03) v1(21.62,30.14) v1(21.62,29.23) v1(21.69,9.19) v1(21.69,8.17) v1(21.82,25.95) v1(21.82,24.81) v1(22.32,14.83) v1(22.32,12.29) v1(22.48,31.03) v1(22.48,29.2) v1(22.43,1.22) v1(22.6,21.24) v1(23.32,11.4)
PGND:
  vias: v1(16.23,42.72) v1(16.87,42.72) v1(16.87,42.08) v1(16.87,41.45) v1(16.87,40.81) v1(16.87,40.18) v1(17.5,42.72) v1(18.26,39.03) v1(18.26,38.4) v1(18.26,37.76) v1(18.26,37.13) v1(18.52,45.38) v1(18.52,44.75) v1(18.52,44.11) v1(18.52,43.48) v1(18.77,39.54) v1(19.15,43.48) v1(19.41,39.54) v1(19.79,43.48)
S0: length 4.4
  BOTTOM w0.305: JP1.2 3.68,28.52 5.52,26.67 U1.3
S1: length 3
  BOTTOM w0.305: JP2.2 U1.2
S2: length 4.4
  BOTTOM w0.305: JP3.2 3.68,21.61 5.52,23.45 U1.1
UNNAMED_3_ADLT8364V2_I56_FBX: length 3.2
  BOTTOM w0.305: R5.2 R6.1 U2.7
UNNAMED_3_ADLT8364V2_I56_INTVCC: length 1.4
  BOTTOM w0.305: U2.4 20.67,27.93 C27.2
UNNAMED_3_ADLT8364V2_I56_RT: length 1.7
  BOTTOM w0.305: R3.2 21.17,22.96 U2.8
UNNAMED_3_ADLT8364V2_I56_SS: length 1.6
  BOTTOM w0.305: U2.9 20.67,22.85 C29.2
UNNAMED_3_ADLT8364V2_I56_VC: length 2
  BOTTOM w0.305: R4.1 23.47,26.87 U2.6
UNNAMED_3_ADM7170_I92_SENSE: length 6
  TOP w0.305: v1(23.53,5.55) 21.42,5.55 v1(20.65,6.32)
  BOTTOM w0.279: v1(20.65,6.32) 20.55,6.41 U4.3
  BOTTOM w0.305: R9.2 v1(23.53,5.55) 23.53,6.17 R10.1
UNNAMED_3_ADM7170_I92_SS: length 1.7
  BOTTOM w0.305: U4.4 20.05,6.71 19.92,6.58 19.92,5.69 C38.2
UNNAMED_3_ADM7171_I103_SS: length 1.3
  BOTTOM w0.279: U5.4 C12.2
UNNAMED_3_CAP_I59_N1: length 1.4
  BOTTOM w0.305: R4.2 C26.1
UNNAMED_3_CN5P3SHLD_I3_N6: length 15.7
  BOTTOM w0.279: P1.SH3 23.86,49.98 22.73,48.85 21.38,48.85 20.18,50.04 P1.SH2 19.19,50.04 17.91,48.77 16.72,48.77 15.51,49.98 P1.SH1
  BOTTOM w0.762: R1.1 16.54,45.38 15.73,46.19 15.73,47.17 15.7,47.2 15.7,49.85 P1.SH1
UNNAMED_3_DIOLED_I28_P: length 1.8
  TOP w0.305: 23.6,13.72 v1(23.6,14.63)
  BOTTOM w0.305: R8.1 v1(23.6,14.63)
UNNAMED_3_DIOSCHOTTKY_I63_P: length 6.5
  BOTTOM w0.508: L5.1 D2.A C30.1
UNNAMED_8_ADT6401_I72_TOVERN: length 46.3
  TOP w0.279: DS2.C 22.28,7.21 20.47,7.21 19.56,6.3 v1(19.56,1.45)
  TOP w0.305: v1(9.29,24.11) 14.48,18.92 14.48,3.81 16.83,1.45 v1(19.56,1.45) 21.09,1.45 v1(22.35,2.71)
  BOTTOM w0.279: U3.5 17.53,1.71 R2.2
  BOTTOM w0.305: U3.2 v1(22.35,2.71) ; v1(19.56,1.45) 19.3,1.71 U3.5 ; v1(9.29,24.11) U1.6
UNNAMED_8_DIOLED_I133_P: length 14.2
  TOP w0.305: v1(15.21,4.7) 15.21,9.45 15.87,10.1 DS2.A
  BOTTOM w0.279: R7.1 v1(15.21,4.7)
VPD: length 78.4
  TOP w0.305: v1(4.95,9.58) C1.2 4.95,12.15 5.53,12.73 U6.2 ; U7.2 5.53,31.18 5.08,30.72 5.08,29.91 C5.2 4.26,29.72 v1(4,29.46)
  TOP w0.318: TP1.1 v1(11.25,35.64)
  BOTTOM w0.305: 0.79,16.15 1.09,15.85 ; 0.79,16.15 0.79,29.84 1.09,30.15 3.32,30.15 v1(4,29.46) 4.45,29.91 4.45,33.92 4.83,34.29 8.33,34.29 9.68,35.64 ; 0.79,16.15 0.79,15.54 ; 1.09,15.85 8.36,15.85 9.27,14.94 9.27,9.14 16.21,2.21 U3.6 U3.3 ; 1.09,15.85 0.79,15.54 ; 0.79,15.54 0.79,11.28 2.49,9.58 v1(4.95,9.58)
  BOTTOM w0.318: v1(11.25,35.64) 9.68,35.64

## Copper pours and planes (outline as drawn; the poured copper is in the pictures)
3V8 on BOTTOM: 20.9,7.44 21.72,7.44 21.72,5.31 21.89,5.13 22.17,5.13 22.28,5.03 22.28,4.04 22.1,3.86 19.86,3.86 19.71,4.01 19.71,4.88 19.86,5.03 20.62,5.03 20.9,5.31
3V8 on L4_PWR: 19.33,18.11 19.33,4.47 12.47,4.47 12.47,1.02 24.38,1.02 24.38,20.68 13.36,20.68 13.36,34.19 10.24,34.19 10.24,28.32 10.97,28.32 10.97,18.11
5V0 on BOTTOM: 17.02,7.47 17.02,6.35 16.84,6.17 16.84,4.9 16.99,4.75 17.45,4.75 17.58,4.88 17.58,6.27 17.81,6.5 17.81,7.47
5V0 on L4_PWR: 19.02,4.8 12.47,4.8 12.47,14.15 0.74,14.15 0.74,40.94 8.61,40.94 8.61,36.68 13.36,36.68 13.36,34.49 9.93,34.49 9.93,28.02 10.67,28.02 10.67,17.81 19.02,17.81
5V6 on BOTTOM: 18.01,16 20.04,16 20.55,15.49 20.55,13.49 20.22,13.16 16.18,13.16 15.9,12.88 15.9,9.8 17.93,9.8 17.93,11.84 18.16,12.07 19.61,12.07 19.84,11.84 19.84,9.82 21.82,9.82 21.82,15.62 22.2,16 22.2,17.02 21.95,17.27 18.01,17.27 17.88,17.15 17.88,16.13
5V_USB on BOTTOM: 21.31,31.88 22.2,31.88 22.33,32 22.33,33.27 22.58,33.53 24.74,33.53 24.74,35.94 21.31,35.94
GND on TOP: 0.64,51.49 12.12,51.49 12.12,50.9 24.76,50.9 24.76,0.64 12.17,0.64 12.17,0 0.64,0 0.64,0.46
GND on BOTTOM: 0.64,0.46 0.64,0.46 0.64,51.49 12.12,51.49 12.12,50.9 24.76,50.9 24.76,0.64 12.17,0.64 12.17,0 0.64,0
GND on L2_GND, L3_GND, L4_PWR, L5_GND: 0.64,51.49 12.12,51.49 12.12,50.9 24.76,50.9 24.76,0.64 12.17,0.64 12.17,0 0.64,0
PGND on TOP, L2_GND, L3_GND, L4_PWR, L5_GND: 15.95,39.04 15.95,50.87 24.74,50.87 24.74,36.7 18.29,36.7
PGND on BOTTOM: 15.95,39.04 15.95,50.87 24.74,50.87 24.74,36.7 18.29,36.7 ; 2 cut-outs
UNNAMED_3_ADLT8364V2_I56_EN on BOTTOM: 15.21,27.18 15.6,27.56 19.41,27.56 19.53,27.43 19.53,26.67 19.66,26.54 20.17,26.54 20.29,26.67 20.29,31.75 20.42,31.88 20.8,31.88 20.93,32 20.93,32.77 20.8,32.89 19.15,32.89 18.9,32.64 18.9,30.23 18.64,29.97 12.42,29.97 12.29,29.85 12.29,27.31 12.42,27.18
UNNAMED_3_ADLT8364V2_I56_SW1 on BOTTOM: 17.25,22.1 18.14,21.21 18.85,21.21 18.85,22.56 19.79,23.5 19.79,24.13 19.66,24.26 15.85,24.26 15.21,24.89 12.42,24.89 12.29,24.77 12.29,22.23 12.42,22.1
UNNAMED_3_CAP_I80_N2 on BOTTOM: 20.8,48.01 20.8,43.82 21.56,43.05 21.56,36.7 24.74,36.7 24.74,48.01

Small or netless copper shapes (teardrops, artwork), in the pictures only: 4 on TOP

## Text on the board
Ref Des/Assembly Bottom: A | C | 3 | 1 | 2
Ref Des/Silkscreen Bottom: 08-059270 REV F Z | SECONDARY SIDE | A | C | WARNING: HOT SURFACE
User.Comments: 6.    SMOOTHEN EDGES AND FREE FROM BURRS AFTER DEPANELIZATION PROCESS | 5.    SINGULATE BOARDS AFTER ASSEMBLY PROCESS. | 4.    PARTS INDICATED BELOW SHOULD BE MOUNTED MANUALLY: | B.    J2, E049020, CONN-PCB SMA END LAUNCH JACK FLAT TAB FLANGE FOR 1.62MM PCB, 60312202114513 | A.    J1, E033180, CONN-PCB SMA END LAUNCH PLUG ROUND FOR 1.62MM PCB, 132365-10 | VIEWED FROM THE | PRIMARY SIDE
Ref Des/Assembly Top: A | C | +
Ref Des/Silkscreen Top: RF OUTPUT | RF INPUT | WARNING: HOT SURFACE | EVAL-CN0523-EBZ | PRIMARY SIDE | 08-059270 REV F Z | A | C
DIMENSION: - | " " | SEE DETAIL A | BOARD DIMENSIONS | (REF) | ARRAY DRAWING | NON-PLATED: +/- 2 MILS | DIA MAX | SEE NOTE 15
PAGE_OUTLINE: J2 | C6 | 02OCT19 | C | D | E | F | B | CHANGES PER ECR-103584 | CHANGES PER ECR-110841 | CHANGES PER ECR-112324 | CHANGES PER ECR-114736 | CHANGES PER ECR-102239 | 29DEC21 | 27OCT22 | 26JAN23 | 01AUG23 | 24MAY21 | Z. ARCEO | PRIMARY SIDE
User.12: 9.    ASSEMBLY VENDOR MUST SOLDER SHORT ON DEFAULT POSITION PIN 1 & 2 OF COMPONENT JP2. | 10.   ASSEMBLY VENDOR MUST SOLDER SHORT ON DEFAULT POSITION PIN 1 & 2 OF COMPONENT JP3. | 8.    ASSEMBLY VENDOR MUST SOLDER SHORT ON DEFAULT POSITION PIN 2 & 3 OF COMPONENT JP1.
User.15: L2-L6: ISOLA 370HR, FR4 OR EQUIVALENT | L5_GND PLANE    (LAYER 5) | L4_PWR PLANE    (LAYER 4) | PERFORMED AFTER CUSTOMER APPROVAL. | 16.    BOARDS TO BE SHIPPED IN  ARRAY AND KEEP INTACT. | 10.    NON-FUNCTIONAL PAD REMOVAL FROM INNER SIGNAL LAYERS MAY BE | PANEL TO BE SUBJECTED TO CUSTOMER'S APPROVAL. | PANELED SOLDER PASTE STENCIL SHOULD BE SENT TO THE CUSTOMER. | ROGERS 4350B | ISOLA 370HR | 10 MILS | 8 MILS | 50 OHMS
User.24: L2 GND | 08-      -07
User.25: L3 GND | 08-      -08
User.26: L4 PWR | 08-      -09
User.27: L5 GND | 08-      -10
User.45: FIGURE | SIZE | 10.0 | 25.0 | 125.0 | 34.0x26.0 | 51.0x24.0 | PLATED | NON-PLATED | DRILL CHART: TOP to BOTTOM | ALL UNITS ARE IN MILS | QTY | 437 | 96 | 4 | 2 | TOLERANCE/NOTES
